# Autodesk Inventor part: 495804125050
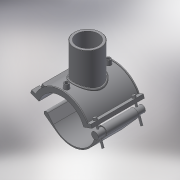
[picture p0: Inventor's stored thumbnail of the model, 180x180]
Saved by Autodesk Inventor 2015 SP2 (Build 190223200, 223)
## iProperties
Created: 2017-07
Part Number: 495804125050
Material: Generic
Description: PLASSON BRANCH SADDLE 125-50
Document SubType Name: Modeling
Designer: KIM
Density: 1 g/cm^3
Appearance: Default
Author: KIM
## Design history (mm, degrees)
derived "495804.ipt"
feature "Solid1::495804.ipt"
feature "Solid2::495804.ipt"
tag "TaggingFeature1"
body "Solid1"
body "Solid2"
other parameters: "d0" = 125, "d2" = 162, "d3" = 31.25, "d4" = 118, "d5" = 0, "d6" = 0.1, "d8" = 0, "d19" = 6, "d20" = 6, "d21" = 70.8, "d23" = 0, "d24" = 35.4, "d26" = 0, "d27" = 3, "d28" = 3, "d29" = 3, "d30" = 41.66667, "d31" = 6, "d32" = 0, "d33" = 0, "d34" = 0.6, "d40" = 76.44, "d41" = 55, "d43" = 0, "d45" = 0, "d47" = 166.5, "d50" = 0, "d70" = 15, "d72" = 0, "d73" = 6, "d75" = 5, "d76" = 0, "d77" = 6.25, "d78" = 92.5, "d79" = 15, "d80" = 47.2, "d82" = 5 deg, "d84" = 4, "d85" = 14, "d86" = 0, "d87" = 3, "d88" = 0, "d89" = 1, "d90" = 1, "d91" = 94.4, "d92" = 0, "d93" = 0.5, "d94" = 65.78947, "d96" = 149.94, "d97" = 2.36, "d98" = 0, "d102" = 1.5, "d105" = 0, "d109" = -31, "d117" = 0.5, "d120" = 140 deg, "d121" = 24.228, "d122" = 20 deg, "d123" = 294, "d124" = 88.2, "d126" = 0, "d143" = 131.25, "d150" = 22.5, "d159" = 4.4, "d161" = 3.125, "d162" = 70.8, "d163" = 0, "d167" = 25, "d168" = 66.81818, "d173" = 1, "d175" = 62.5, "d176" = 20 deg, "d177" = 8.75, "d178" = 22, "d180" = 0, "d185" = 38.35, "d186" = 38.35, "d187" = 73.5, "d188" = 6.6, "d189" = 8.75, "d190" = 0, "d191" = 110.25, "d200" = 11, "d202" = 0, "d216" = 106.2, "d217" = 0, "d221" = 43.66, "d222" = 8.75, "d223" = 5.25, "d224" = 62.5, "d225" = 5.25, "d227" = 18, "d230" = 77.5, "d236" = 20 deg, "d237" = 80.5, "d238" = 20 deg, "d239" = 8.75, "d_" = 125, "B_" = 162, "H_" = 93, "L_" = 118, "d_t" = 6, "H_1" = 82, "d1" = 147, "d148" = 3.125, "d160" = 3.125
